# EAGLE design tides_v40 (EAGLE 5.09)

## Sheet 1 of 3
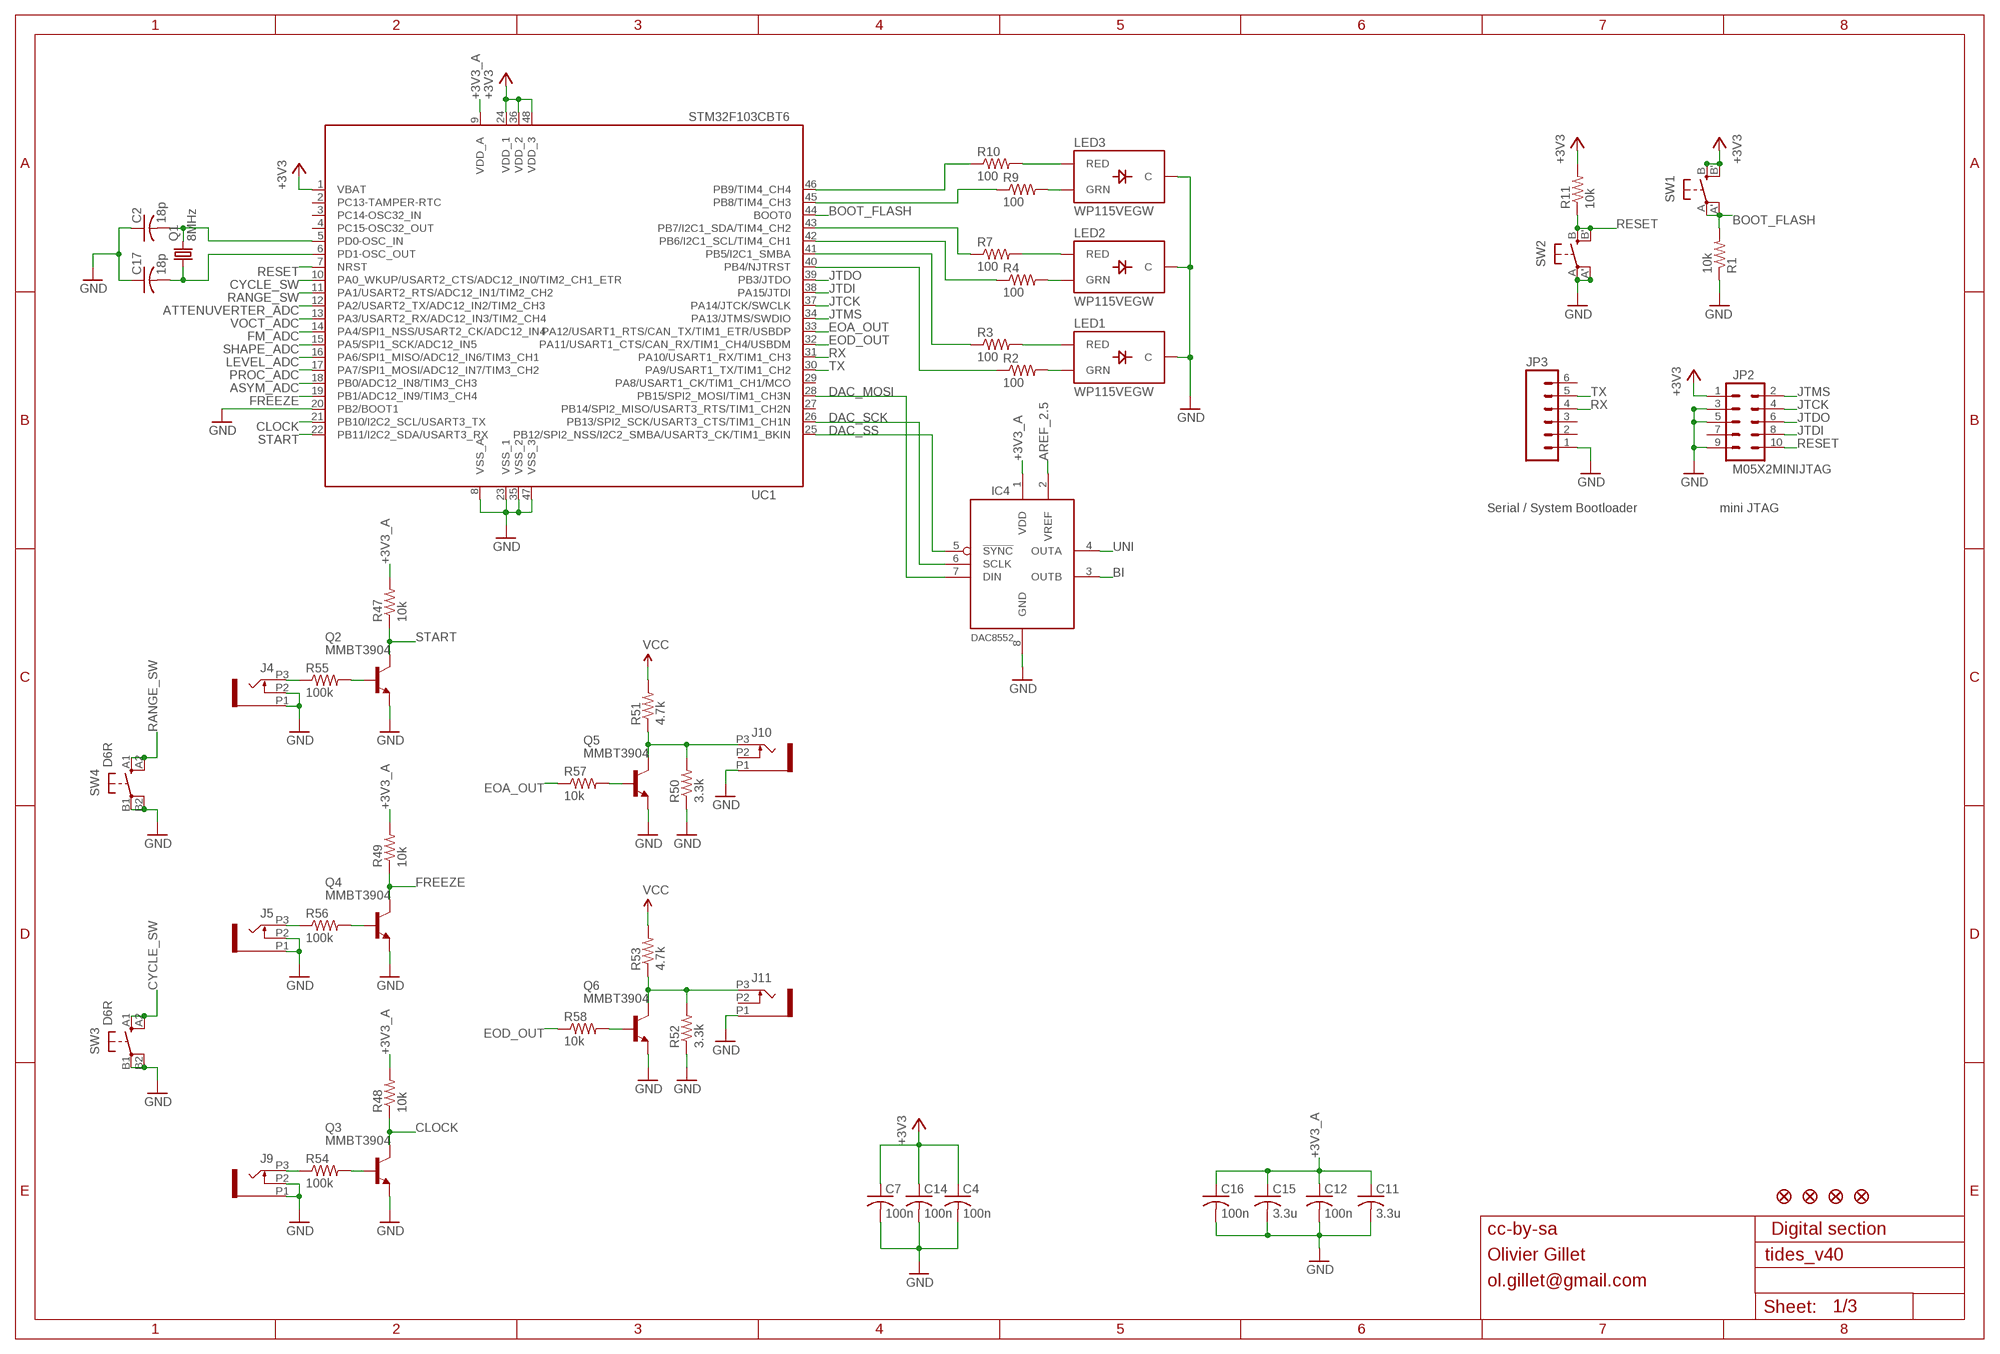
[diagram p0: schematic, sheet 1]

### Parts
C2  18p  C-USC0603  [C0603]
C4  100n  C-USC0603  [C0603]
C7  100n  C-USC0603  [C0603]
C11  3.3u  C-USC0603  [C0603]
C12  100n  C-USC0603  [C0603]
C14  100n  C-USC0603  [C0603]
C15  3.3u  C-USC0603  [C0603]
C16  100n  C-USC0603  [C0603]
C17  18p  C-USC0603  [C0603]
IC4  DAC8552  [MSOP-8]
J4  PJ301_THONKICONN6  [WQP_PJ_301M6]
J5  PJ301_THONKICONN6  [WQP_PJ_301M6]
J9  PJ301_THONKICONN6  [WQP_PJ_301M6]
J10  PJ301_THONKICONN6  [WQP_PJ_301M6]
J11  PJ301_THONKICONN6  [WQP_PJ_301M6]
JP2  M05X2MINIJTAG  [2X5-1.27]
JP3  M06SIP  [1X06]
JP4  FIDUCIAL1X2  [FIDUCIAL-1X2]
JP5  FIDUCIAL1X2  [FIDUCIAL-1X2]
JP6  FIDUCIAL1X2  [FIDUCIAL-1X2]
JP7  FIDUCIAL1X2  [FIDUCIAL-1X2]
LED1  WP115VEGW  LED-BICOLOR-THROUGHHOLE  [LED-BICOLOR-THROUGHHOLE]
LED2  WP115VEGW  LED-BICOLOR-THROUGHHOLE  [LED-BICOLOR-THROUGHHOLE]
LED3  WP115VEGW  LED-BICOLOR-THROUGHHOLE  [LED-BICOLOR-THROUGHHOLE]
Q1  8MHz  CRYSTALHC49UP  [HC49UP]
Q2  MMBT3904  MMBT3904LT1-NPN-SOT23-BEC  [SOT23-BEC]
Q3  MMBT3904  MMBT3904LT1-NPN-SOT23-BEC  [SOT23-BEC]
Q4  MMBT3904  MMBT3904LT1-NPN-SOT23-BEC  [SOT23-BEC]
Q5  MMBT3904  MMBT3904LT1-NPN-SOT23-BEC  [SOT23-BEC]
Q6  MMBT3904  MMBT3904LT1-NPN-SOT23-BEC  [SOT23-BEC]
R1  10k  R-US_R0603  [R0603]
R2  100  R-US_R0603  [R0603]
R3  100  R-US_R0603  [R0603]
R4  100  R-US_R0603  [R0603]
R7  100  R-US_R0603  [R0603]
R9  100  R-US_R0603  [R0603]
R10  100  R-US_R0603  [R0603]
R11  10k  R-US_R0603  [R0603]
R47  10k  R-US_R0603  [R0603]
R48  10k  R-US_R0603  [R0603]
R49  10k  R-US_R0603  [R0603]
R50  3.3k  R-US_R0603  [R0603]
R51  4.7k  R-US_R0603  [R0603]
R52  3.3k  R-US_R0603  [R0603]
R53  4.7k  R-US_R0603  [R0603]
R54  100k  R-US_R0603  [R0603]
R55  100k  R-US_R0603  [R0603]
R56  100k  R-US_R0603  [R0603]
R57  10k  R-US_R0603  [R0603]
R58  10k  R-US_R0603  [R0603]
SW1  EVQQ2  [EVQ-Q2]
SW2  EVQQ2  [EVQ-Q2]
SW3  D6R  [D6R]
SW4  D6R  [D6R]
UC1  STM32F103CBT6  STM32F103CB  [LQFP48]

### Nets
+3V3: C4.1 C7.1 C14.1 JP2.1 R11.2 SW1.B'(S1) SW1.B(S) UC1.1(VBAT) UC1.24(VDD_1) UC1.36(VDD_2) UC1.48(VDD_3) ; also sheet 3
+3V3_A: C11.1 C12.1 C15.1 C16.1 IC4.1(VDD) R47.2 R48.2 R49.2 UC1.9(VDD_A) ; also sheet 2,3
AREF_2.5: IC4.2(VREF) ; also sheet 3
ASYM_ADC: UC1.18(PB0/ADC12_IN8/TIM3_CH3) ; also sheet 2
ATTENUVERTER_ADC: UC1.12(PA2/USART2_TX/ADC12_IN2/TIM2_CH3) ; also sheet 2
BI: IC4.3(OUTB) ; also sheet 2
BOOT_FLASH: R1.2 SW1.A'(P1) SW1.A(P) UC1.44(BOOT0)
CLOCK: Q3.C R48.1 UC1.21(PB10/I2C2_SCL/USART3_TX)
CYCLE_SW: SW3.A1(S) SW3.A2(S1) UC1.10(PA0_WKUP/USART2_CTS/ADC12_IN0/TIM2_CH1_ETR)
DAC_MOSI: IC4.7(DIN) UC1.28(PB15/SPI2_MOSI/TIM1_CH3N)
DAC_SCK: IC4.6(SCLK) UC1.26(PB13/SPI2_SCK/USART3_CTS/TIM1_CH1N)
DAC_SS: IC4.5(!SYNC) UC1.25(PB12/SPI2_NSS/I2C2_SMBA/USART3_CK/TIM1_BKIN)
EOA_OUT: R57.1 UC1.33(PA12/USART1_RTS/CAN_TX/TIM1_ETR/USBDP)
EOD_OUT: R58.1 UC1.32(PA11/USART1_CTS/CAN_RX/TIM1_CH4/USBDM)
FM_ADC: UC1.14(PA4/SPI1_NSS/USART2_CK/ADC12_IN4) ; also sheet 2
FREEZE: Q4.C R49.1 UC1.19(PB1/ADC12_IN9/TIM3_CH4)
GND: C2.1 C4.2 C7.2 C11.2 C12.2 C14.2 C15.2 C16.2 C17.1 IC4.8(GND) J4.P1 J4.P2 J5.P1 J5.P2 J9.P1 J9.P2 J10.P1 J11.P1 JP2.3 JP2.5 JP2.9 JP3.1 LED1.2(C) LED2.2(C) LED3.2(C) Q2.E Q3.E Q4.E Q5.E Q6.E R1.1 R50.1 R52.1 SW2.A'(P1) SW2.A(P) SW3.B1(P) SW3.B2(P1) SW4.B1(P) SW4.B2(P1) UC1.8(VSS_A) UC1.20(PB2/BOOT1) UC1.23(VSS_1) UC1.35(VSS_2) UC1.47(VSS_3) ; also sheet 2,3
JTCK: JP2.4 UC1.37(PA14/JTCK/SWCLK)
JTDI: JP2.8 UC1.38(PA15/JTDI)
JTDO: JP2.6 UC1.39(PB3/JTDO)
JTMS: JP2.2 UC1.34(PA13/JTMS/SWDIO)
LEVEL_ADC: UC1.16(PA6/SPI1_MISO/ADC12_IN6/TIM3_CH1) ; also sheet 2
N$7: C2.2 Q1.2 UC1.5(PD0-OSC_IN)
N$8: C17.2 Q1.1 UC1.6(PD1-OSC_OUT)
N$21: J5.P3 R56.1
N$23: Q4.B R56.2
N$24: J9.P3 R54.1
N$25: Q3.B R54.2
N$26: Q6.B R58.2
N$27: J11.P3 Q6.C R52.2 R53.1
N$28: LED3.3(RED) R10.2
N$29: LED3.1(GRN) R9.2
N$30: LED2.3(RED) R7.2
N$31: LED2.1(GRN) R4.2
N$32: LED1.3(RED) R3.2
N$33: LED1.1(GRN) R2.2
N$34: R10.1 UC1.46(PB9/TIM4_CH4)
N$35: R9.1 UC1.45(PB8/TIM4_CH3)
N$36: R7.1 UC1.43(PB7/I2C1_SDA/TIM4_CH2)
N$37: R4.1 UC1.42(PB6/I2C1_SCL/TIM4_CH1)
N$38: R3.1 UC1.41(PB5/I2C1_SMBA)
N$39: R2.1 UC1.40(PB4/NJTRST)
N$44: J10.P3 Q5.C R50.2 R51.1
N$47: Q5.B R57.2
N$57: J4.P3 R55.1
N$66: Q2.B R55.2
PROC_ADC: UC1.17(PA7/SPI1_MOSI/ADC12_IN7/TIM3_CH2) ; also sheet 2
RANGE_SW: SW4.A1(S) SW4.A2(S1) UC1.11(PA1/USART2_RTS/ADC12_IN1/TIM2_CH2)
RESET: JP2.10 R11.1 SW2.B'(S1) SW2.B(S) UC1.7(NRST)
RX: JP3.4 UC1.31(PA10/USART1_RX/TIM1_CH3)
SHAPE_ADC: UC1.15(PA5/SPI1_SCK/ADC12_IN5) ; also sheet 2
START: Q2.C R47.1 UC1.22(PB11/I2C2_SDA/USART3_RX)
TX: JP3.5 UC1.30(PA9/USART1_TX/TIM1_CH2)
UNI: IC4.4(OUTA) ; also sheet 2
VCC: R51.2 R53.2 ; also sheet 2,3
VOCT_ADC: UC1.13(PA3/USART2_RX/ADC12_IN3/TIM2_CH4) ; also sheet 2
Unconnected: J10.P2 J11.P2 JP2.7 JP3.2 JP3.3 JP3.6 UC1.2(PC13-TAMPER-RTC) UC1.3(PC14-OSC32_IN) UC1.4(PC15-OSC32_OUT) UC1.27(PB14/SPI2_MISO/USART3_RTS/TIM1_CH2N) UC1.29(PA8/USART1_CK/TIM1_CH1/MCO)

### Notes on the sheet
- Serial / System Bootloader | mini JTAG
- cc-by-sa | Digital section
- Olivier Gillet
- ol.gillet@gmail.com

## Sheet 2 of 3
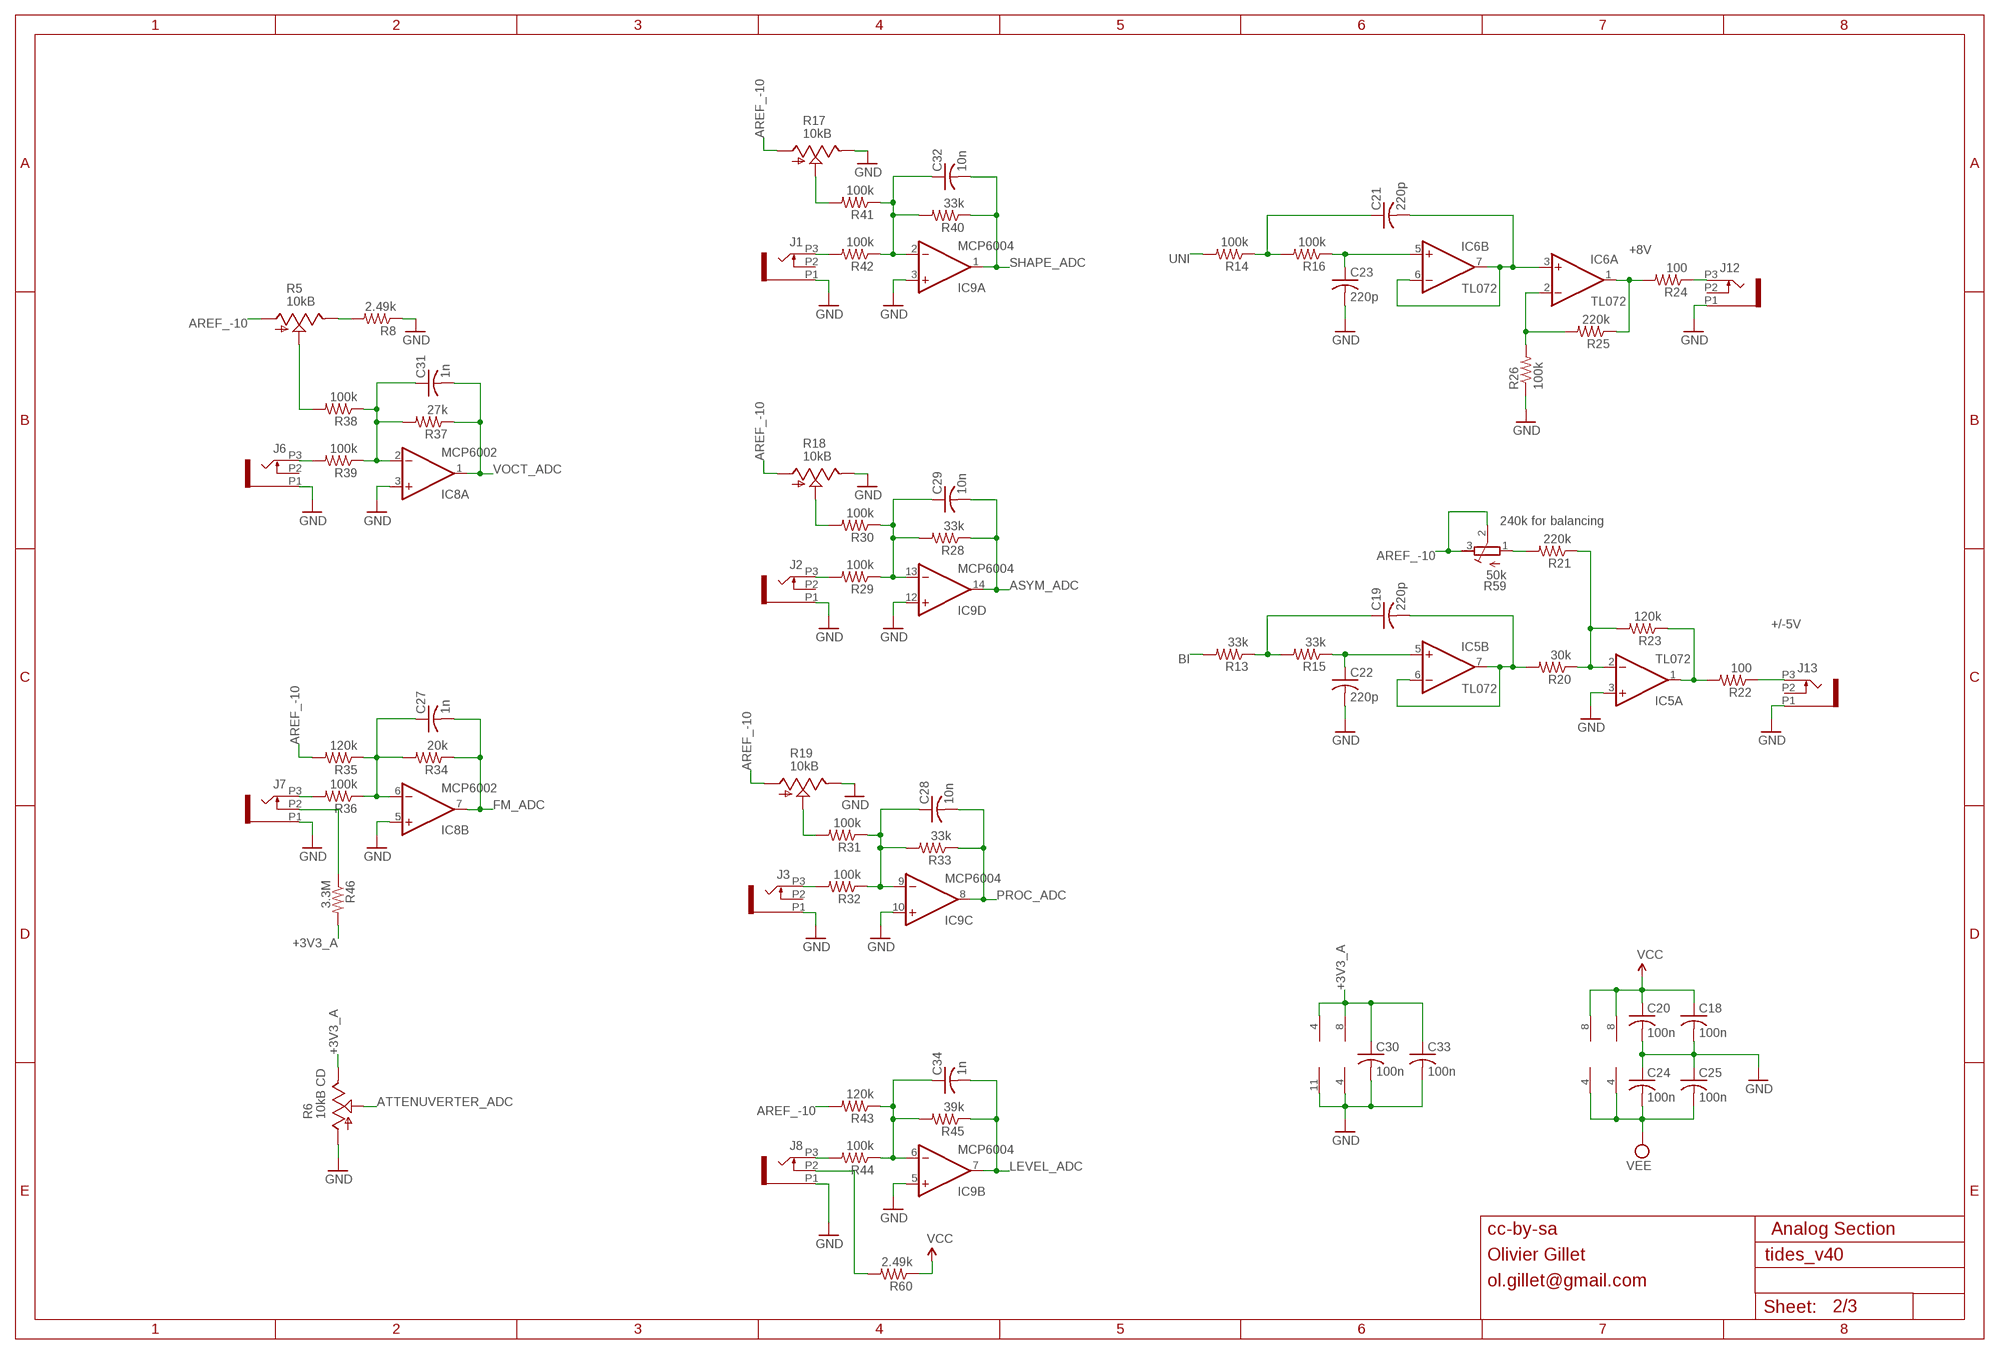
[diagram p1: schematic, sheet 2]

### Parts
C18  100n  C-USC0603  [C0603]
C19  220p  C-USC0603  [C0603]
C20  100n  C-USC0603  [C0603]
C21  220p  C-USC0603  [C0603]
C22  220p  C-USC0603  [C0603]
C23  220p  C-USC0603  [C0603]
C24  100n  C-USC0603  [C0603]
C25  100n  C-USC0603  [C0603]
C27  1n  C-USC0603  [C0603]
C28  10n  C-USC0603  [C0603]
C29  10n  C-USC0603  [C0603]
C30  100n  C-USC0603  [C0603]
C31  1n  C-USC0603  [C0603]
C32  10n  C-USC0603  [C0603]
C33  100n  C-USC0603  [C0603]
C34  1n  C-USC0603  [C0603]
IC5  TL072  TL072D  [SO08]
IC6  TL072  TL072D  [SO08]
IC8  MCP6002  TL072D  [SO08]
IC9  MCP6004  TL074D  [SO14]
J1  PJ301_THONKICONN6  [WQP_PJ_301M6]
J2  PJ301_THONKICONN6  [WQP_PJ_301M6]
J3  PJ301_THONKICONN6  [WQP_PJ_301M6]
J6  PJ301_THONKICONN6  [WQP_PJ_301M6]
J7  PJ301_THONKICONN6  [WQP_PJ_301M6]
J8  PJ301_THONKICONN6  [WQP_PJ_301M6]
J12  PJ301_THONKICONN6  [WQP_PJ_301M6]
J13  PJ301_THONKICONN6  [WQP_PJ_301M6]
R5  10kB  POT_USVERTICAL_PS  [ALPS_POT_VERTICAL_PS]
R6  10kB CD  POT_USVERTICAL_PS  [ALPS_POT_VERTICAL_PS]
R8  2.49k  R-US_R0603  [R0603]
R13  33k  R-US_R0603  [R0603]
R14  100k  R-US_R0603  [R0603]
R15  33k  R-US_R0603  [R0603]
R16  100k  R-US_R0603  [R0603]
R17  10kB  POT_USVERTICAL_PS  [ALPS_POT_VERTICAL_PS]
R18  10kB  POT_USVERTICAL_PS  [ALPS_POT_VERTICAL_PS]
R19  10kB  POT_USVERTICAL_PS  [ALPS_POT_VERTICAL_PS]
R20  30k  R-US_R0603  [R0603]
R21  220k  R-US_R0603  [R0603]
R22  100  R-US_R0603  [R0603]
R23  120k  R-US_R0603  [R0603]
R24  100  R-US_R0603  [R0603]
R25  220k  R-US_R0603  [R0603]
R26  100k  R-US_R0603  [R0603]
R28  33k  R-US_R0603  [R0603]
R29  100k  R-US_R0603  [R0603]
R30  100k  R-US_R0603  [R0603]
R31  100k  R-US_R0603  [R0603]
R32  100k  R-US_R0603  [R0603]
R33  33k  R-US_R0603  [R0603]
R34  20k  R-US_R0603  [R0603]
R35  120k  R-US_R0603  [R0603]
R36  100k  R-US_R0603  [R0603]
R37  27k  R-US_R0603  [R0603]
R38  100k  R-US_R0603  [R0603]
R39  100k  R-US_R0603  [R0603]
R40  33k  R-US_R0603  [R0603]
R41  100k  R-US_R0603  [R0603]
R42  100k  R-US_R0603  [R0603]
R43  120k  R-US_R0603  [R0603]
R44  100k  R-US_R0603  [R0603]
R45  39k  R-US_R0603  [R0603]
R46  3.3M  R-US_R0603  [R0603]
R59  50k  R-TRIMM3296X  [RTRIM3296X]
R60  2.49k  R-US_R0805  [R0805]

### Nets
+3V3_A: C30.1 C33.1 IC8.8(P:V+) IC9.4(P:V+) R6.P$1(E) R46.2 ; also sheet 1,3
AREF_-10: R5.P$3(A) R17.P$3(A) R18.P$3(A) R19.P$3(A) R35.2 R43.2 R59.2(S) R59.3(A) ; also sheet 3
ASYM_ADC: C29.2 IC9.14(D:OUT) R28.1 ; also sheet 1
ATTENUVERTER_ADC: R6.P$2(S) ; also sheet 1
BI: R13.2 ; also sheet 1
BI_OUT: IC5.1(A:OUT) R22.2 R23.1
F_CV: IC5.2(A:-IN) R20.1 R21.1 R23.2
FM_ADC: C27.2 IC8.7(B:OUT) R34.1 ; also sheet 1
GND: C18.2 C20.2 C22.2 C23.2 C24.1 C25.1 C30.2 C33.2 IC5.3(A:+IN) IC8.3(A:+IN) IC8.4(P:V-) IC8.5(B:+IN) IC9.3(A:+IN) IC9.5(B:+IN) IC9.10(C:+IN) IC9.11(P:V-) IC9.12(D:+IN) J1.P1 J2.P1 J3.P1 J6.P1 J7.P1 J8.P1 J12.P1 J13.P1 R6.P$3(A) R8.1 R17.P$1(E) R18.P$1(E) R19.P$1(E) R26.1 ; also sheet 1,3
LEVEL_ADC: C34.2 IC9.7(B:OUT) R45.1 ; also sheet 1
N$1: J1.P3 R42.2
N$2: C32.1 IC9.2(A:-IN) R40.2 R41.1 R42.1
N$3: R17.P$2(S) R41.2
N$4: J2.P3 R29.2
N$5: C29.1 IC9.13(D:-IN) R28.2 R29.1 R30.1
N$6: J7.P2 R46.1
N$9: R18.P$2(S) R30.2
N$10: J3.P3 R32.2
N$11: C28.1 IC9.9(C:-IN) R31.1 R32.1 R33.2
N$12: R19.P$2(S) R31.2
N$13: J8.P3 R44.2
N$14: C34.1 IC9.6(B:-IN) R43.1 R44.1 R45.2
N$15: J6.P3 R39.2
N$16: C31.1 IC8.2(A:-IN) R37.2 R38.1 R39.1
N$17: R5.P$2(S) R38.2
N$18: J13.P3 R22.1
N$19: R5.P$1(E) R8.2
N$20: J7.P3 R36.2
N$22: C27.1 IC8.6(B:-IN) R34.2 R35.1 R36.1
N$40: R21.2 R59.1(E)
N$41: IC6.2(A:-IN) R25.2 R26.2
N$42: C19.2 IC5.6(B:-IN) IC5.7(B:OUT) R20.2
N$43: C22.1 IC5.5(B:+IN) R15.1
N$45: C19.1 R13.1 R15.2
N$46: IC6.1(A:OUT) R24.2 R25.1
N$48: J8.P2 R60.2
N$67: C21.2 IC6.3(A:+IN) IC6.6(B:-IN) IC6.7(B:OUT)
N$69: C23.1 IC6.5(B:+IN) R16.1
N$71: C21.1 R14.1 R16.2
PROC_ADC: C28.2 IC9.8(C:OUT) R33.1 ; also sheet 1
SHAPE_ADC: C32.2 IC9.1(A:OUT) R40.1 ; also sheet 1
UNI: R14.2 ; also sheet 1
UNI_OUT: J12.P3 R24.1
VCC: C18.1 C20.1 IC5.8(P:V+) IC6.8(P:V+) R60.1 ; also sheet 1,3
VEE: C24.2 C25.2 IC5.4(P:V-) IC6.4(P:V-) ; also sheet 3
VOCT_ADC: C31.2 IC8.1(A:OUT) R37.1 ; also sheet 1
Unconnected: J1.P2 J2.P2 J3.P2 J6.P2 J12.P2 J13.P2

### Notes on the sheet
- +8V
- 240k for balancing
- +/-5V
- cc-by-sa | Analog Section
- Olivier Gillet
- ol.gillet@gmail.com

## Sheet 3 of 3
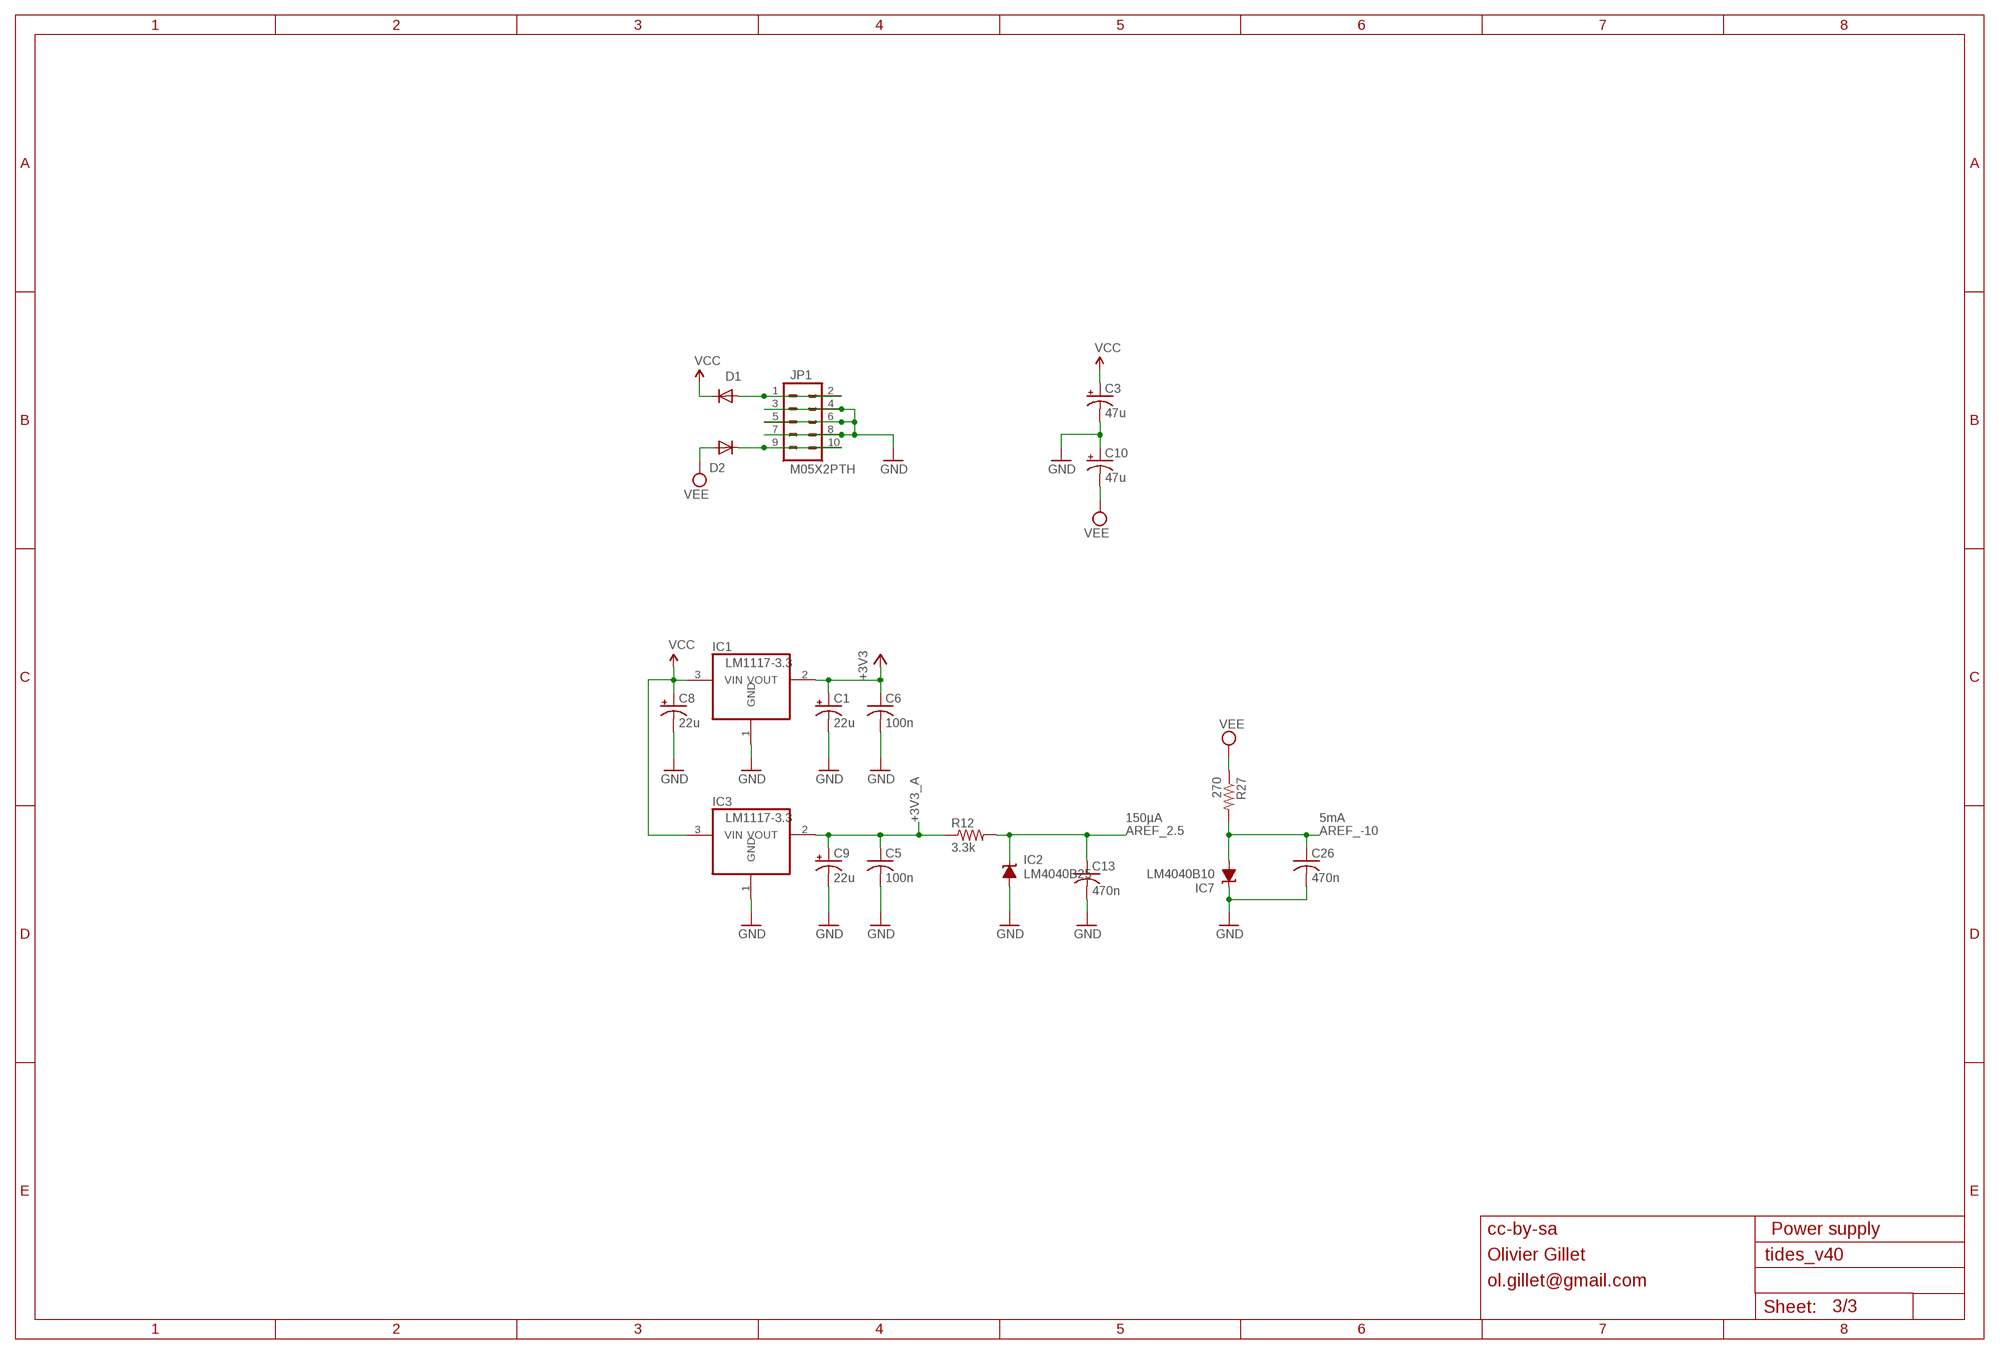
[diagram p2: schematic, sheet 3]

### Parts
C1  22u  CPOL-USC  [PANASONIC_C]
C3  47u  CPOL-USD  [PANASONIC_D]
C5  100n  C-USC0603  [C0603]
C6  100n  C-USC0603  [C0603]
C8  22u  CPOL-USC  [PANASONIC_C]
C9  22u  CPOL-USC  [PANASONIC_C]
C10  47u  CPOL-USD  [PANASONIC_D]
C13  470n  C-USC0603  [C0603]
C26  470n  C-USC0603  [C0603]
D1  1N5819HW  DIODE-SOD123  [SOD123]
D2  1N5819HW  DIODE-SOD123  [SOD123]
IC1  LM1117-3.3  REG1117  [SOT223]
IC2  LM4040B25  LM4041B12DBZ  [DBZ_R-PDSO-G3]
IC3  LM1117-3.3  REG1117  [SOT223]
IC7  LM4040B10  LM4041B12DBZ  [DBZ_R-PDSO-G3]
JP1  M05X2PTH  [AVR_ICSP]
R12  3.3k  R-US_R0603  [R0603]
R27  270  R-US_R0603  [R0603]

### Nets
+3V3: C1.+ C6.1 IC1.2(VOUT) ; also sheet 1
+3V3_A: C5.1 C9.+ IC3.2(VOUT) R12.1 ; also sheet 1,2
AREF_2.5: C13.1 IC2.1(C) R12.2 ; also sheet 1
AREF_-10: C26.1 IC7.2(A) R27.2 ; also sheet 2
GND: C1.- C3.- C5.2 C6.2 C8.- C9.- C10.+ C13.2 C26.2 IC1.1(GND) IC2.2(A) IC3.1(GND) IC7.1(C) JP1.3 JP1.4 JP1.5 JP1.6 JP1.7 JP1.8 ; also sheet 1,2
N$56: D1.A JP1.1 JP1.2
N$64: D2.C JP1.9 JP1.10
VCC: C3.+ C8.+ D1.C IC1.3(VIN) IC3.3(VIN) ; also sheet 1,2
VEE: C10.- D2.A R27.1 ; also sheet 2

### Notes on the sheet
- 150µA | 5mA
- cc-by-sa | Power supply
- Olivier Gillet
- ol.gillet@gmail.com

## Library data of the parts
C1 C3 C8-C10 = rcl:CPOL-US: POLARIZED CAPACITOR, American symbol
C2 C4-C7 C11-C34 = rcl:C-US: CAPACITOR, American symbol
D1 D2 = diode:DIODE-: DIODE
IC1 IC3 = og-vreg:REG1117: 800mA and 1A Low Dropout (LDO) Positive Regulator 1.8V, 2.5V, 2.85V, 3.3V, 5V, and Adj
IC2 IC7 = texas:LM4041: PRECISION MICROPOWER SHUNT VOLTAGE REFERENCE
IC4 = og-dac:DAC8552
IC5 IC6 IC8 = linear:TL072: OP AMP
IC9 = gm-ics:TL074: OP AMP
J1-J13 = og-pj301_variations:PJ301_THONKICONN
JP1 JP2 = og-header:M05X2: Header 5x2 Standard 10-pin dual row 0.1" header. Commonly used with AVR-ISP. Use with Spark Fun Electronics SKU: PRT-00778
JP3 = SparkFun:M06: Header 6 Standard 6-pin 0.1" header. Use with straight break away headers (SKU : PRT-00116), right angle break away headers (PRT-00553), swiss pins (PRT-00743), machine pins (PRT-00117), and female headers (PRT-00115). Molex polarized connector foot print use with SKU : PRT-08094 with associated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
JP4-JP7 = SparkFun:FIDUCIAL: Fiducial Alignment Points
LED1-LED3 = og-leds:LED-BICOLOR-THROUGHHOLE
Q1 = crystal:CRYSTAL: CRYSTAL
Q2-Q6 = transistor:*-NPN-: NPN Transistror BF959 corrected 2008.03.06
R1-R4 R7-R16 R20-R58 R60 = rcl:R-US_: RESISTOR, American symbol
R5 R6 R17-R19 = pot-alps:POT_US
R59 = rcl:R-TRIMM: Trimm resistor
SW1 SW2 = adafruit:EVQQ2: SMT 6mm switch, EVQQ2 series http://www.ladyada.net/library/eagle
SW3 SW4 = og-switch:D6R: C&K D6R
UC1 = stm32:STM32F103CB

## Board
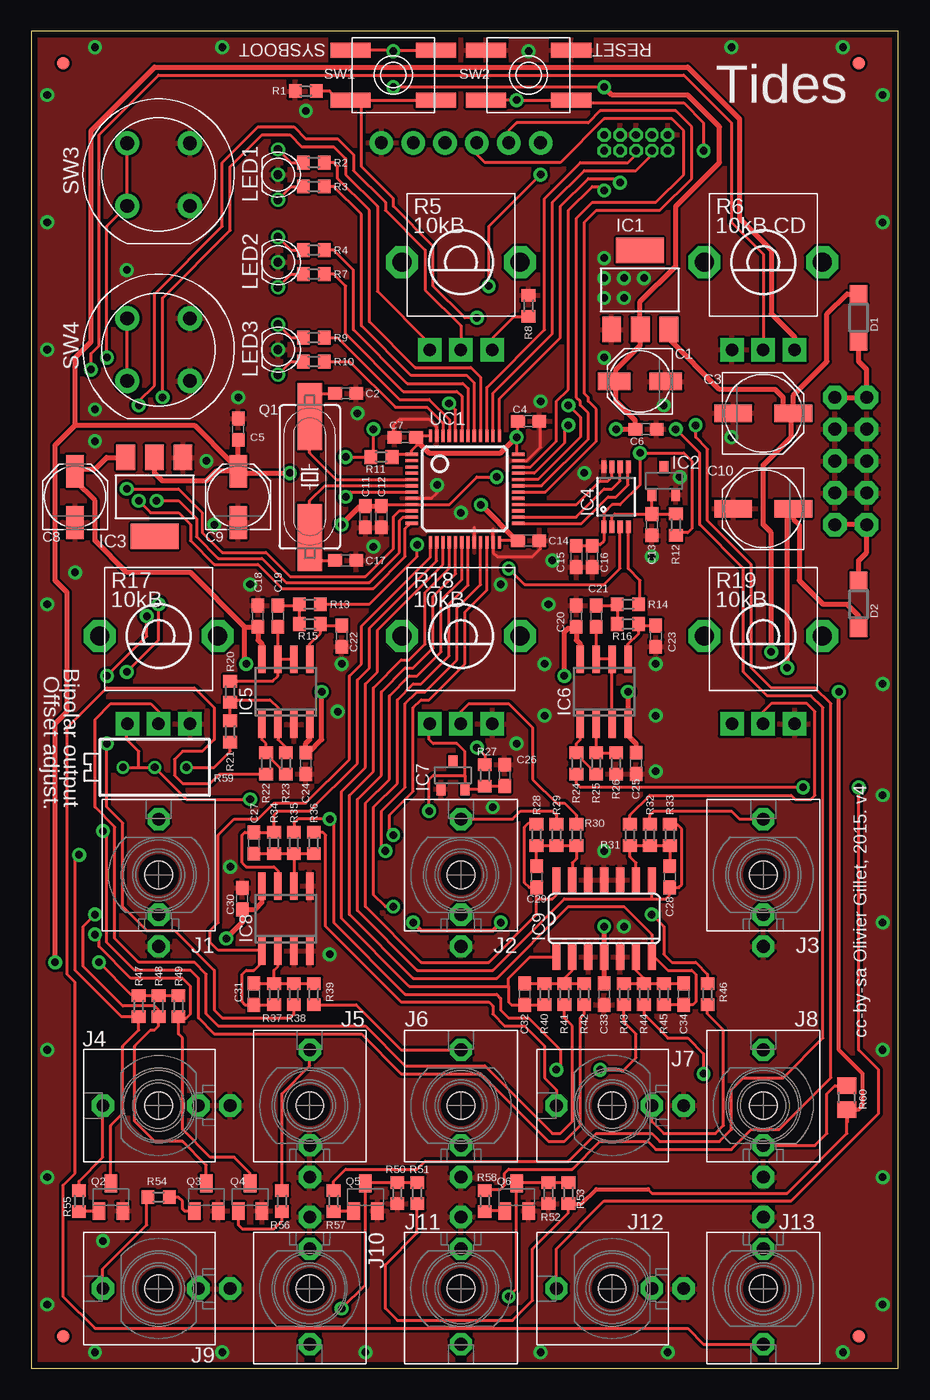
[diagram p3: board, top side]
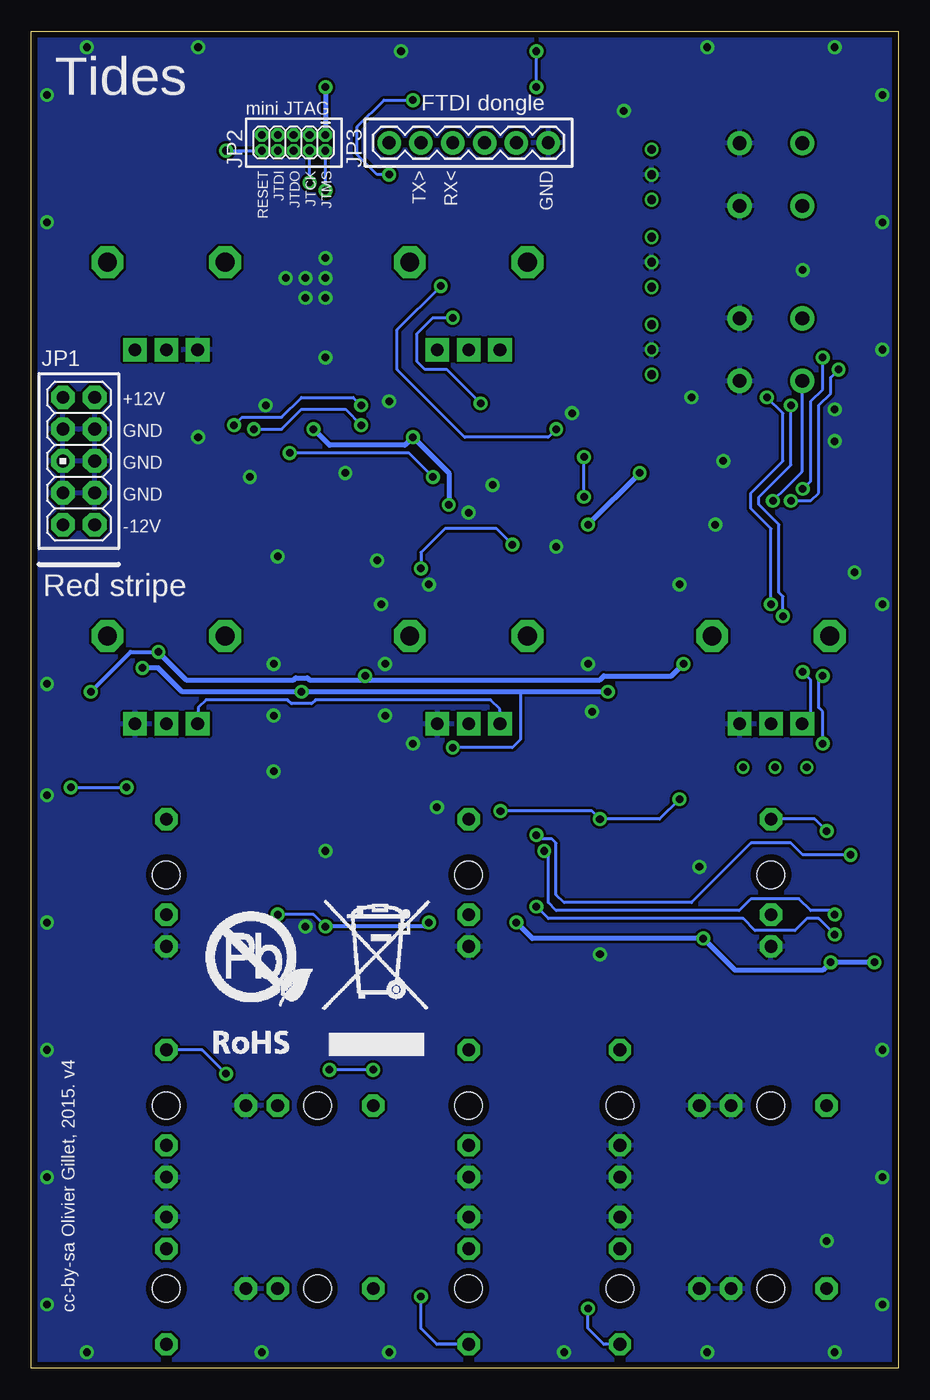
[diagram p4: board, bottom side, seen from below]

Size 69.19 x 106.68 mm. Coordinates in mm from the lower left corner, seen from the top.
Outline: 0,0 69.19,0 69.19,106.68 0,106.68 0,0
Copper layers (1*16): Top 0.035mm / dielectric 1.5mm / Bottom 0.035mm
Design rules "PCBCart-Standard": minimum track width 8mil, minimum drill 0.4mm, track to track 8mil, track to pad 8mil, pad to pad 8mil, via to via 8mil, smd to smd 8mil, copper to edge 20mil, drill to drill 8mil, minimum pad ring 8mil, minimum via ring 10mil, stop-mask expansion 3mil, vias tented up to drill 25mil, thermal gap 8mil

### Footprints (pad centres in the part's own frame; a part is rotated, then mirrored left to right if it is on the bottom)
PANASONIC_C = smd 2.6 x 1.4: + 2.05,0; - -2.05,0
C0603 = smd 1.1 x 1: 1 -0.85,0; 2 0.85,0
PANASONIC_D = smd 3 x 1.4: + 2.4,0; - -2.4,0
SOD123 = smd 1.4 x 1.4: A 1.9,0; C -1.9,0
SOT223 = smd 1.499 x 2.007: 1 -2.261,-3.15; 2 0.025,-3.15; 3 2.311,-3.15 | smd 3.81 x 2.007: 4 0,3.15
DBZ_R-PDSO-G3 = smd 0.7 x 1: 1 -0.95,-1.1; 2 0.95,-1.1; 3 0,1.1
MSOP-8 = smd 0.41 x 1.02: 1 -0.975,-2.4; 2 -0.325,-2.4; 3 0.325,-2.4; 4 0.975,-2.4; 5 0.975,2.4; 6 0.325,2.4; 7 -0.325,2.4; 8 -0.975,2.4
SO08 = smd 0.6 x 2.2: 1 -1.905,-2.6; 2 -0.635,-2.6; 3 0.635,-2.6; 4 1.905,-2.6; 5 1.905,2.6; 6 0.635,2.6; 7 -0.635,2.6; 8 -1.905,2.6
SO14 = smd 0.66 x 2.032: 1 -3.81,-3.073; 2 -2.54,-3.073; 3 -1.27,-3.073; 4 0,-3.073; 5 1.27,-3.073; 6 2.54,-3.073; 7 3.81,-3.073; 8 3.81,3.073; 9 2.54,3.073; 10 1.27,3.073; 11 0,3.073; 12 -1.27,3.073; 13 -2.54,3.073; 14 -3.81,3.073
WQP_PJ_301M6 = drill 1.016 pad 1.778 octagon: P1 0,-5.715; P2 0,-3.175; P3 0,4.445 | hole 2.2: 0,0
AVR_ICSP = drill 1.016 pad 1.88 octagon: 1 -1.27,5.08; 2 1.27,5.08; 3 -1.27,2.54; 4 1.27,2.54; 5 -1.27,0; 6 1.27,0; 7 -1.27,-2.54; 8 1.27,-2.54; 9 -1.27,-5.08; 10 1.27,-5.08
2X5-1.27 = drill 0.61 pad 1.067 octagon: 1 -1.27,3.81; 2 0,3.81; 3 -1.27,2.54; 4 0,2.54; 5 -1.27,1.27; 6 0,1.27; 7 -1.27,0; 8 0,0; 9 -1.27,-1.27; 10 0,-1.27
1X06 = drill 1.016 pad 1.88 round: 1 0,0; 2 2.54,0; 3 5.08,0; 4 7.62,0; 5 10.16,0; 6 12.7,0
FIDUCIAL-1X2 = smd 1 x 1: 1 0,0
LED-BICOLOR-THROUGHHOLE = drill 0.7 round: 1 -2,0; 2 0,0; 3 2,0
HC49UP = smd 5.334 x 1.93: 1 -4.826,0; 2 4.826,0
SOT23-BEC = smd 1 x 1.4: B -0.95,-1.1; C 0,1.1; E 0.95,-1.1
R0603 = smd 1 x 1.1: 1 -0.85,0; 2 0.85,0
ALPS_POT_VERTICAL_PS = drill 1 pad 1.88 square: P$1 -2.5,7; P$2 0,7; P$3 2.5,7 | drill 1.5 pad 2.54 octagon: P$4 -4.7,0; P$5 4.7,0
RTRIM3296X = drill 0.61 round: 1 0,-2.54; 2 0,0; 3 0,2.54
R0805 = smd 1.3 x 1.5: 1 -0.95,0; 2 0.95,0
EVQ-Q2 = smd 3.2 x 1.2: A -3.4,-2; A' 3.4,-2; B -3.4,2; B' 3.4,2
D6R = drill 1.1 pad 1.93 round: A1 -2.5,2.5; A2 2.5,2.5; B1 -2.5,-2.5; B2 2.5,-2.5
LQFP48 = smd 0.254 x 1: 1 -2.75,-4.25; 2 -2.25,-4.25; 3 -1.75,-4.25; 4 -1.25,-4.25; 5 -0.75,-4.25; 6 -0.25,-4.25; 7 0.25,-4.25; 8 0.75,-4.25; 9 1.25,-4.25; 10 1.75,-4.25; 11 2.25,-4.25; 12 2.75,-4.25; 25 2.75,4.25; 26 2.25,4.25; 27 1.75,4.25; 28 1.25,4.25; 29 0.75,4.25; 30 0.25,4.25; 31 -0.25,4.25; 32 -0.75,4.25; 33 -1.25,4.25; 34 -1.75,4.25; 35 -2.25,4.25; 36 -2.75,4.25 | smd 1 x 0.254: 13 4.25,-2.75; 14 4.25,-2.25; 15 4.25,-1.75; 16 4.25,-1.25; 17 4.25,-0.75; 18 4.25,-0.25; 19 4.25,0.25; 20 4.25,0.75; 21 4.25,1.25; 22 4.25,1.75; 23 4.25,2.25; 24 4.25,2.75; 37 -4.25,2.75; 38 -4.25,2.25; 39 -4.25,1.75; 40 -4.25,1.25; 41 -4.25,0.75; 42 -4.25,0.25; 43 -4.25,-0.25; 44 -4.25,-0.75; 45 -4.25,-1.25; 46 -4.25,-1.75; 47 -4.25,-2.25; 48 -4.25,-2.75

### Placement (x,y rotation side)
C1  48.58,78.74 180 top
C2  25.08,77.79 180 top
C3  58.42,76.2 0 top
C4  39.69,75.56 0 top
C5  16.51,74.93 90 top
C6  49.05,74.93 0 top
C7  29.84,74.3 180 top
C8  3.49,69.53 90 top
C9  16.51,69.53 90 top
C10  58.42,68.58 180 top
C11  26.67,67.94 270 top
C12  27.94,67.94 270 top
C13  49.53,67.31 270 top
C14  39.69,66.04 0 top
C15  43.5,64.77 270 top
C16  44.77,64.77 270 top
C17  25.08,64.45 180 top
C18  18.1,60.01 90 top
C19  19.68,60.01 270 top
C20  43.5,60.01 90 top
C21  45.09,60.01 270 top
C22  24.77,58.42 270 top
C23  49.85,58.42 270 top
C24  21.91,48.26 90 top
C25  48.26,48.26 90 top
C26  37.78,47.31 90 top
C27  17.78,41.91 90 top
C28  50.96,39.21 270 top
C29  40.32,39.21 270 top
C30  16.83,37.47 90 top
C31  17.78,29.84 270 top
C32  39.37,29.84 270 top
C33  45.72,29.84 270 top
C34  52.07,29.84 270 top
D1  66.04,83.82 270 top
D2  66.04,60.96 270 top
IC1  48.58,86.04 0 top
IC2  50.48,70.8 0 top
IC3  9.84,69.53 180 top
IC4  46.67,69.53 0 top
IC5  20.32,53.98 0 top
IC6  45.72,53.98 0 top
IC7  33.66,47.31 0 top
IC8  20.32,35.88 0 top
IC9  45.72,35.88 0 top
J1  10.16,39.37 0 top
J2  34.29,39.37 0 top
J3  58.42,39.37 0 top
J4  10.16,20.95 90 top
J5  22.23,20.95 0 top
J6  34.29,20.95 0 top
J7  46.35,20.95 90 top
J8  58.42,20.95 0 top
J9  10.16,6.35 90 top
J10  22.23,6.35 180 top
J11  34.29,6.35 180 top
J12  46.35,6.35 90 top
J13  58.42,6.35 180 top
JP1  65.41,72.39 0 bottom
JP2  49.53,97.16 270 bottom
JP3  27.94,97.79 180 bottom
JP4  2.54,104.14 0 top
JP5  66.04,104.14 0 top
JP6  2.54,2.54 0 top
JP7  66.04,2.54 0 top
LED1  19.68,95.25 270 top
LED2  19.68,88.27 270 top
LED3  19.68,81.28 270 top
Q1  22.23,71.12 90 top
Q2  6.35,13.65 0 top
Q3  13.97,13.65 0 top
Q4  17.46,13.65 0 top
Q5  26.67,13.65 0 top
Q6  38.73,13.65 0 top
R1  21.91,101.92 0 top
R2  22.54,96.2 180 top
R3  22.54,94.3 180 top
R4  22.54,89.22 180 top
R5  34.29,88.27 180 top
R6  58.42,88.27 180 top
R7  22.54,87.31 180 top
R8  39.69,84.77 270 top
R9  22.54,82.23 180 top
R10  22.54,80.33 180 top
R11  27.94,72.71 0 top
R12  51.44,67.31 90 top
R13  22.23,60.96 0 top
R14  47.62,60.96 0 top
R15  22.23,59.37 180 top
R16  47.62,59.37 180 top
R17  10.16,58.42 180 top
R18  34.29,58.42 180 top
R19  58.42,58.42 180 top
R20  15.88,53.98 90 top
R21  15.88,50.8 270 top
R22  18.73,48.26 90 top
R23  20.32,48.26 90 top
R24  43.5,48.26 90 top
R25  45.09,48.26 90 top
R26  46.67,48.26 90 top
R27  36.2,47.31 270 top
R28  40.32,42.55 270 top
R29  41.91,42.55 90 top
R30  43.5,42.55 90 top
R31  47.78,42.55 90 top
R32  49.37,42.55 90 top
R33  50.96,42.55 270 top
R34  19.37,41.91 270 top
R35  20.95,41.91 90 top
R36  22.54,41.91 90 top
R37  19.37,29.84 90 top
R38  20.95,29.84 270 top
R39  22.54,29.84 270 top
R40  40.96,29.84 90 top
R41  42.55,29.84 270 top
R42  44.13,29.84 270 top
R43  47.31,29.84 270 top
R44  48.9,29.84 270 top
R45  50.48,29.84 90 top
R46  53.98,29.84 90 top
R47  8.57,28.89 90 top
R48  10.16,28.89 90 top
R49  11.75,28.89 90 top
R50  29.21,13.97 90 top
R51  30.8,13.97 270 top
R52  41.27,13.97 90 top
R53  42.86,13.97 270 top
R54  10.16,13.65 0 top
R55  3.81,13.34 270 top
R56  20,13.34 270 top
R57  24.13,13.34 270 top
R58  36.2,13.34 270 top
R59  9.84,47.94 90 top
R60  65.09,21.59 90 top
SW1  28.89,103.19 0 top
SW2  39.69,103.19 180 top
SW3  10.16,95.25 90 top
SW4  10.16,81.28 90 top
U$3  [ROHS_BIG]  56.52,24.13 0 bottom
UC1  34.61,70.17 270 top

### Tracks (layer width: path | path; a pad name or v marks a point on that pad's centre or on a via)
+3V3  (via drill 0.6)
  Top 0.254: 32.38,105.09 SW1.B' 28.99,105.19 v28.89,105.09 28.8,105.19 SW1.B | C7.1 30.82,74.42 UC1.48 | 30.7,74.08 30.8,73.98 30.8,73.66 30.36,73.22 UC1.1 29,72.92 R11.2 | C4.1 38.84,74.4 v38.73,74.3 38.73,73.04 UC1.36 | v45.72,102.23 v28.89,102.23 | UC1.24 37.48,66.04 C14.1
  Top 0.406: v45.72,102.23 46.35,101.6 52.39,101.6 54.93,99.06 54.93,96.2 51.44,92.71 51.44,87.95 48.58,85.09 48.58,82.92 IC1.2 48.6,81.62 46.67,79.69 46.67,78.89 C1.+ 46.67,78.59 46.67,77.15 48.2,75.62 C6.1 v46.67,74.93 | v38.73,74.3 37.47,73.03 31.75,73.03 30.7,74.08 C7.1 | v35.88,68.9 38.73,66.04 C14.1
  Bottom 0.254: v28.89,102.23 v28.89,105.09 28.89,105.19
  Bottom 0.406: v45.72,102.23 JP2.1 | v46.67,74.93 45.4,73.66 39.37,73.66 v38.73,74.3 35.88,71.44 v35.88,68.9
+3V3_A  (via drill 0.6)
  Top 0.254: C12.1 28.06,68.92 UC1.9 33.36,68.92 35.56,71.12 v37.15,71.12 | C15.1 C16.1 44.87,65.72 45.4,65.72 45.7,66.02 IC4.1 45.7,68.24 46.35,68.9 46.99,68.9 48.58,70.48 v48.58,73.03 52.07,73.03 52.7,72.39 52.7,66.99 52.39,66.67 51.65,66.67 R12.1 | R6.P$1 60.96,81.31 | v5.4,32.38 7.94,29.84 8.47,29.84 R47.2 R48.2 R49.2 | R46.2 53.98,31.43 53.02,32.38 51.12,32.38 50.48,33.02 50.48,35.24 v49.53,36.2
  Top 0.305: v30.48,35.56 31.11,34.92 36.83,34.92 v37.47,35.56
  Top 0.406: IC3.2 9.84,72.66 9.84,71.44 10.48,70.8 13.97,70.8 14.75,71.58 C9.+ | 16.51,72.39 C5.1 | C9.+ 16.68,71.75 17,71.44 v20.64,71.44 | 16.51,72.39 C9.+ | 16.51,72.39 15.88,72.39 13.02,75.25 3.49,75.25 | v45.72,35.24 IC9.4 C33.1 | IC8.8 18.41,37.15 17.88,36.62 C30.1 16.83,35.56 v15.56,34.29 | v24.77,67.31 26.25,68.8 C11.1 C12.1 | R6.P$1 60.92,82.27 59.05,84.14 59.05,89.22 56.52,91.76 56.52,99.69 52.39,103.82 9.84,103.82 4.76,98.74 4.76,81.92 3.49,80.64 3.49,75.25 | v1.91,32.38 1.91,51.44 2.86,52.39 2.86,61.91 1.91,62.87 1.91,73.66 3.49,75.25
  Bottom 0.254: v48.58,73.03 39.05,73.03 v37.15,71.12 | v49.53,36.2 46.67,36.2 v45.72,35.24
  Bottom 0.305: v37.47,35.56 37.78,35.24 v45.72,35.24
  Bottom 0.406: v20.64,71.44 v24.77,67.31 | v30.48,35.56 29.21,34.29 v15.56,34.29 13.02,31.75 6.03,31.75 v5.4,32.38 v1.91,32.38
AREF_2.5
  Top 0.254: IC4.2 46.35,67.94 46.57,68.16 C13.1 | C13.1 IC2.1 | C13.1 R12.2
AREF_-10  (via drill 0.6)
  Top 0.254: C26.1 R27.2 35.95,46.21 IC7.2 | R18.P$3 31.75,51.38 31.75,50.16 32.07,49.85 33.97,49.85 34.6,49.22 34.6,47.31 | IC7.2 | R35.2 20.95,43.5 21.27,43.81 v23.81,43.81 24.13,43.5 24.13,35.56 29.84,29.84 37.15,29.84 37.47,29.53 37.47,28.57 38.1,27.94 39.69,27.94 42.23,25.4 42.23,24.13 v41.91,23.81 | v45.4,23.81 47.31,23.81 48.26,24.77 48.26,26.67 47.31,27.62 R43.2 | v10.16,60.96 10.16,58.1 v7.62,55.56 | 34.6,47.31 IC7.2 | v31.75,44.45 31.75,46.99 32.07,47.31 34.6,47.31 | v10.48,77.47 10.48,85.41 15.88,90.81 15.88,95.89 18.41,98.42 20.64,98.42 21.59,97.47 24.13,97.47 25.08,96.52 25.08,95.25 27.62,92.71 27.62,85.94 31.79,81.77 R5.P$3 | R59.3 8.57,47.94 | 8.57,47.94 R59.2 12.38,45.4 v17.46,45.4 | R17.P$3 7.62,51.38 7.62,50.16 8.57,49.21 8.57,47.94
  Bottom 0.254: v31.75,44.45 24.45,44.45 v23.81,43.81 19.05,43.81 v17.46,45.4 | v41.91,23.81 v45.4,23.81 | v10.48,77.47 9.21,76.2 9.21,72.39 11.75,69.85 11.75,68.58 10.16,66.99 v10.16,60.96 | v7.62,55.56 6.99,54.93 6.99,52.09 R17.P$3 | R19.P$3 55.88,51.46 55.88,52.7 55.24,53.34 48.74,53.34 48.42,53.02 46.83,53.02 46.51,53.34 32.54,53.34 31.79,52.59 R18.P$3
ASYM_ADC
  Top 0.254: UC1.18 34.36,62.93 32.7,61.28 32.7,57.15 30.8,55.24 30.16,55.24 28.57,53.66 28.57,46.99 26.67,45.09 26.67,36.83 31.11,32.38 36.51,32.38 40.32,36.2 40.32,37.47 | R28.1 40.22,43.5 39.69,43.5 39.37,43.18 39.37,38.73 39.74,38.36 C29.2 40.32,37.47 | IC9.14 41.91,37.78 41.59,37.47 40.32,37.47
ATTENUVERTER_ADC  (via drill 0.6)
  Top 0.254: R6.P$2 58.42,88.9 55.88,91.44 55.88,99.38 52.07,103.19 10.16,103.19 5.4,98.42 5.4,81.6 4.76,80.96 v4.76,79.69 | v8.57,69.22 9.53,68.26 11.75,68.26 12.7,67.31 12.7,66.04 14.61,64.14 18.1,64.14 20,62.23 27.3,62.23 29.84,64.77 29.84,66.99 30.27,67.42 UC1.12
  Bottom 0.254: v4.76,79.69 5.4,79.06 5.4,77.79 6.35,76.83 6.35,69.85 6.99,69.22 v8.57,69.22
BI  (via drill 0.6)
  Top 0.254: IC4.3 46.99,63.82 45.72,62.55 39.37,62.55 v38.1,63.82 | R13.2 26.99,60.96 30.8,64.77 v30.8,65.72
  Bottom 0.254: v30.8,65.72 32.07,66.99 36.2,66.99 38.1,65.09 v38.1,63.82
BI_OUT
  Top 0.254: IC5.1 18.41,50.16 18.73,49.85 R22.2 18.73,49 R23.1
BOOT_FLASH  (via drill 0.6)
  Top 0.254: 26.35,101.19 SW1.A | 26.35,101.19 SW1.A' | SW1.A 25.4,101.09 | v33.34,76.99 33.86,76.47 UC1.44 | 26.35,101.19 26.35,95.89 28.89,93.34 28.89,92.71 32.07,89.53 32.07,86.36 34.61,83.82 v35.56,83.82 | R1.2 23.81,101.92 24.54,101.19 SW1.A
  Bottom 0.254: v33.34,76.99 36.04,79.69 37.78,79.69 38.42,80.33 38.42,82.55 37.15,83.82 v35.56,83.82
CLOCK  (via drill 0.6)
  Top 0.254: Q3.C 13.97,16.19 12.06,18.1 9.84,18.1 8.26,19.68 8.26,25.72 9.53,26.99 9.84,26.99 10.16,27.3 R48.1 10.16,28.57 9.84,28.89 7.3,28.89 4.13,32.07 4.13,35.24 v5.08,36.2 | UC1.21 35.86,62.53 33.97,60.64 33.97,56.52 31.43,53.98 30.8,53.98 29.84,53.02 29.84,46.35 27.94,44.45 27.94,41.59 v28.26,41.27
  Bottom 0.254: v28.26,41.27 27.94,40.96 27.94,37.15 27.3,36.51 12.7,36.51 11.75,37.47 7.94,37.47 6.99,36.51 5.4,36.51 v5.08,36.2
CYCLE_SW  (via drill 0.6)
  Top 0.254: SW3.A2 SW3.A1 6.03,91.12 v6.03,80.64 | UC1.10 29.37,68.42 28.89,67.94 28.89,65.41 26.67,63.18 20.64,63.18 18.73,65.09 15.24,65.09 13.65,66.67 13.65,68.26 11.75,70.17 v7.62,70.17
  Bottom 0.254: v7.62,70.17 6.99,70.8 6.99,77.15 6.03,78.11 v6.03,80.64
DAC_MOSI
  Top 0.254: IC4.7 46.35,71.12 46.04,70.8 45.4,70.8 43.52,68.92 UC1.28
DAC_SCK
  Top 0.254: IC4.6 46.99,70.8 46.35,70.17 45.72,70.17 43.47,67.92 UC1.26
DAC_SS
  Top 0.254: IC4.5 47.62,71.91 47.62,70.48 46.67,69.53 46.04,69.53 43.92,67.42 UC1.25
EOA_OUT  (via drill 0.6)
  Top 0.254: UC1.33 40.14,71.42 42.55,73.82 42.55,74.93 v42.86,75.25 | v51.44,74.93 53.34,73.03 53.34,67.31 56.83,63.82 56.83,55.56 58.74,53.66 62.23,53.66 63.18,52.7 63.18,26.35 60.01,23.18 56.83,23.18 55.88,22.23 55.88,19.05 54.93,18.1 50.16,18.1 49.53,18.73 45.09,18.73 42.86,16.51 31.43,16.51 30.8,15.88 25.08,15.88 24.13,14.92 R57.1
  Bottom 0.254: v51.44,74.93 49.21,74.93 47.62,76.52 44.13,76.52 v42.86,75.25
EOD_OUT  (via drill 0.6)
  Top 0.254: UC1.32 40.44,70.92 43.81,74.3 43.81,75.88 v42.86,76.83 | v53.02,75.25 53.02,74.3 53.98,73.34 53.98,67.63 57.47,64.14 57.47,55.88 59.05,54.29 62.55,54.29 63.82,53.02 63.82,23.18 59.69,19.05 57.47,19.05 55.88,17.46 49.85,17.46 49.21,18.1 45.4,18.1 43.18,15.88 38.1,15.88 37.78,15.56 37.78,14.61 37.47,14.29 36.3,14.29 R58.1
  Bottom 0.254: v53.02,75.25 52.39,75.88 49.21,75.88 47.62,77.47 43.5,77.47 v42.86,76.83
F_CV
  Top 0.254: R23.2 20.32,49.53 19.68,50.16 IC5.2 19.68,52.7 19.05,53.34 16.09,53.34 R20.1 R21.1
FM_ADC
  Top 0.254: IC8.7 19.68,39.69 19.37,40.01 17.14,40.01 16.83,40.32 16.83,42.55 17.04,42.76 C27.2 R34.1 19.37,44.13 19.68,44.45 22.23,44.45 26.04,48.26 26.04,54.93 26.99,55.88 26.99,59.05 32.36,64.42 UC1.14
FREEZE  (via drill 0.6)
  Top 0.254: Q4.C 17.46,15.56 16.19,16.83 14.29,16.83 12.06,19.05 12.06,26.35 11.75,26.67 R49.1 11.85,27.94 12.38,27.94 12.7,28.26 12.7,30.48 12.06,31.11 7.94,31.11 5.4,33.66 5.4,34.29 v5.08,34.61 | UC1.19 34.86,62.48 33.34,60.96 33.34,56.83 31.11,54.61 30.48,54.61 29.21,53.34 29.21,46.67 27.3,44.77 27.3,37.78 28.26,36.83 v28.89,36.83
  Bottom 0.254: v28.89,36.83 27.94,35.88 12.38,35.88 11.43,34.92 8.26,34.92 7.3,35.88 6.35,35.88 v5.08,34.61
GND  (via drill 0.6)
  Top 0.254: C4.2 40.64,75.46 40.64,73.5 39.56,72.42 UC1.35 | v32.38,70.48 32.38,69.85 31.95,69.42 UC1.8 | C7.2 28.89,74.4 28.89,75.25 29.37,75.72 31.75,75.72 32.36,75.12 UC1.47 | UC1.20 35.36,67.11 | 36.86,66.97 UC1.23 36.86,65.06 37.15,64.77 40.01,64.77 40.64,65.41 40.64,65.94 C14.2
  other vias: 49.85,56.2 51.75,71.12 17.46,62.55 41.59,64.45 40.64,77.15 26.04,76.2 27.3,65.56 14.61,67.31 13.97,72.39 50.48,76.83 55.88,74.3 45.72,85.41 39.69,105.09 21.91,100.33 24.77,56.2 49.85,47.62 15.88,40.01 47.31,35.24 45.72,41.27 36.83,44.77 34.29,68.26 41.27,60.96 49.53,64.77 16.51,77.47 3.49,63.5 38.73,49.85 24.45,52.39 40.96,56.2 23.81,33.02 40.96,52.07 7.62,87.63 5.08,105.41 15.24,105.41 55.88,105.41 64.77,105.41 1.27,101.6 1.27,91.44 1.27,81.28 1.27,60.96 1.27,25.4 1.27,15.24 1.27,5.08 5.08,1.27 15.24,1.27 26.67,1.27 40.64,1.27 50.8,1.27 64.77,1.27 67.94,5.08 67.94,15.24 67.94,25.4 67.94,35.56 67.94,45.72 67.94,54.61 67.94,101.6 67.94,91.44 37.47,62.55 44.13,71.44 49.85,52.07 45.72,87 47.31,87 48.9,87 45.72,80.64 45.72,88.58 47.31,85.41 5.08,73.98 5.08,76.52 5.71,10.16
  pour Bottom: 0,106.68 0,0 69.22,0 69.22,106.68
  pour Top (isolate 0.203): 0,106.68 0,0 69.22,0 69.22,106.68
JTCK  (via drill 0.6)
  Top 0.254: v46.99,94.61 46.67,94.93 44.45,94.93 42.23,92.71 42.23,82.23 37.36,77.36 UC1.37
  Bottom 0.254: v46.99,94.61 JP2.4
JTDI
  Top 0.254: JP2.8 49.53,96.84 48.26,95.57 44.13,95.57 41.59,93.03 41.59,82.55 36.86,77.81 UC1.38
JTDO
  Top 0.254: JP2.6 48.26,96.84 47.62,96.2 43.81,96.2 40.96,93.34 40.96,82.87 36.36,78.27 UC1.39
JTMS  (via drill 0.6)
  Top 0.254: v45.72,93.98 45.4,94.3 44.77,94.3 42.86,92.39 42.86,78.11 41.91,77.15 41.91,73.98 39.85,71.92 UC1.34
  Bottom 0.254: v45.72,93.98 JP2.2
LEVEL_ADC
  Top 0.254: R45.1 C34.2 52.81,29 53.02,29.21 53.02,31.43 52.7,31.75 50.8,31.75 49.75,32.8 IC9.7 49.53,34.61 47.31,36.83 42.86,36.83 37.15,31.11 30.48,31.11 25.4,36.2 25.4,45.72 27.3,47.62 27.3,54.29 29.53,56.52 30.16,56.52 31.43,57.78 31.43,61.91 33.36,63.84 UC1.16
N$1  (via drill 0.6)
  Top 0.254: R42.2 44.13,28.26 43.81,27.94 43.81,19.37 42.55,18.1 41.27,18.1 35.88,23.5 29.53,23.5 26.35,26.67 14.61,26.67 13.34,27.94 13.34,31.11 12.7,31.75 8.26,31.75 6.03,33.97 6.03,42.55 v5.71,42.86
  Bottom 0.254: v5.71,42.86 6.67,43.81 J1.P3
N$2
  Top 0.254: C32.1 39.37,30.8 39.47,30.7 R40.2 R41.1 | R41.1 R42.1 | IC9.2 43.18,31.75 42.55,31.11 R41.1
N$3
  Top 0.254: R17.P$2 10.16,52.39 9.53,53.02 6.35,53.02 5.08,51.75 5.08,44.77 6.67,43.18 6.67,34.29 8.57,32.38 13.02,32.38 13.97,31.43 13.97,28.26 14.92,27.3 26.67,27.3 29.84,24.13 36.2,24.13 41.59,18.73 42.23,18.73 43.18,19.68 43.18,27.3 42.55,27.94 R41.2
N$4
  Top 0.254: R29.2 41.91,44.13 41.59,44.45 39.05,44.45 38.42,43.81 J2.P3
N$5
  Top 0.254: C29.1 | C29.1 R28.2 R29.1 R30.1 43.5,40.64 43.18,40.32 IC9.13
N$6
  Top 0.254: R46.1 53.98,28.26 55.24,26.99 55.24,19.37 54.61,18.73 50.48,18.73 49.53,19.68 J7.P2
N$7
  Top 0.254: UC1.5 24.33,70.92 22.23,73.03 Q1.2 22.23,77.47 22.54,77.79 C2.2
N$8
  Top 0.254: UC1.6 23.43,70.42 22.23,69.22 Q1.1 22.23,64.77 22.54,64.45 C17.2
N$9
  Top 0.254: R30.2 43.5,44.13 42.55,45.09 41.91,45.09 40.01,46.99 40.01,51.12 38.1,53.02 34.92,53.02 34.29,52.39 R18.P$2
N$10
  Top 0.254: R32.2 49.37,44.13 49.69,44.45 55.88,44.45 56.52,43.81 J3.P3
N$11
  Top 0.254: C28.1 R33.2 R32.1 R31.1 47.78,40.8 48.26,40.32 IC9.9
N$12
  Top 0.254: R31.2 47.78,44.13 49.37,45.72 60.64,45.72 60.96,45.4 62.23,45.4 62.55,45.72 62.55,52.39 61.91,53.02 59.05,53.02 58.42,52.39 R19.P$2
N$13  (via drill 0.6)
  Top 0.254: R44.2 48.9,28.26 50.8,26.35 52.39,26.35 53.66,25.08 v53.66,23.5
  Bottom 0.254: v53.66,23.5 55.56,25.4 J8.P3
N$14
  Top 0.254: R43.1 R44.1 | R44.1 R45.2 C34.1 | IC9.6 48.26,31.75 48.9,31.11 R44.1
N$15
  Top 0.254: R39.2 25.93,29 29.53,25.4 J6.P3
N$16
  Top 0.254: C31.1 R37.2 | R37.2 R38.1 R39.1 | R37.2 19.37,31.75 19.68,32.07 IC8.2
N$17  (via drill 0.6)
  Top 0.254: R5.P$2 34.29,83.19 31.43,86.04 31.43,89.22 28.26,92.39 28.26,93.03 25.72,95.57 25.72,96.84 24.45,98.11 21.91,98.11 20.95,99.06 18.1,99.06 15.24,96.2 15.24,91.12 9.84,85.72 9.84,78.42 8.57,77.15 v8.57,76.83 | R38.2 20.95,28.26 20.64,27.94 15.24,27.94 14.61,28.57 14.61,31.75 11.43,34.92 9.21,34.92 7.3,36.83 7.3,43.5 6.03,44.77 v6.03,49.85 | v9.21,60.01 9.21,58.42 v6.03,55.24
  Bottom 0.254: v8.57,76.83 8.57,72.07 11.11,69.53 11.11,68.9 9.53,67.31 9.53,61.91 9.21,61.59 v9.21,60.01 | v6.03,49.85 6.03,52.39 6.35,52.7 6.35,54.93 v6.03,55.24
N$18
  Top 0.254: R22.1 15.03,47.41 14.29,46.67 12.06,46.67 11.43,47.31 11.43,48.58 12.06,49.21 13.65,49.21 14.61,50.16 14.61,52.7 13.02,54.29 6.03,54.29 2.86,51.12 2.86,31.43 3.49,30.8 3.49,15.56 2.54,14.61 2.54,5.71 5.08,3.17 52.39,3.17 53.66,1.91 J13.P3
N$19
  Top 0.254: R5.P$1 36.83,81.31 36.83,82.23 38.52,83.92 R8.2
N$20
  Top 0.254: R36.2 23.28,42.76 23.5,42.55 23.5,35.24 29.53,29.21 36.51,29.21 36.83,28.89 36.83,28.26 37.78,27.3 39.37,27.3 40.96,25.72 40.96,23.18 41.91,22.23 J7.P3
N$21
  Top 0.254: R56.1 20,21.91 22.23,24.13 J5.P3
N$22
  Top 0.254: R35.1 IC8.6 | R35.1 R34.2 C27.1 | R35.1 R36.1
N$23
  Top 0.254: Q4.B 16.51,11.43 16.83,11.11 19.37,11.11 20,11.75 R56.2
N$24
  Top 0.254: R54.1 9.21,13.55 9.21,11.43 5.71,7.94 J9.P3
N$25
  Top 0.254: R54.2 11.75,13.65 12.06,13.34 12.06,12.7 12.21,12.55 Q3.B
N$26
  Top 0.254: R58.2 36.26,12.55 Q6.B
N$27  (via drill 0.6)
  Top 0.254: R53.1 R52.2 38.8,14.82 Q6.C 38.73,6.35 v38.1,5.71
  Bottom 0.254: v38.1,5.71 38.1,3.17 36.83,1.91 J11.P3
N$28
  Top 0.254: LED3.3 20.73,80.33 R10.2
N$29
  Top 0.254: LED3.1 20.73,82.23 R9.2
N$30
  Top 0.254: LED2.3 20.73,87.31 R7.2
N$31
  Top 0.254: LED2.1 20.73,89.22 R4.2
N$32
  Top 0.254: LED1.3 20.73,94.3 R3.2
N$33
  Top 0.254: LED1.1 20.73,96.2 R2.2
N$34
  Top 0.254: R10.1 25.4,80.33 29.05,76.68 31.59,76.68 32.86,75.41 UC1.46
N$35
  Top 0.254: R9.1 24.45,82.23 29.37,77.31 31.75,77.31 33.36,75.7 UC1.45
N$36
  Top 0.254: R7.1 24.13,87.31 25.08,86.36 25.08,82.55 29.69,77.95 33.97,77.95 34.36,77.56 UC1.43
N$37
  Top 0.254: R4.1 24.13,89.22 25.72,87.63 25.72,82.87 30,78.58 34.45,78.58 34.86,78.17 UC1.42
N$38
  Top 0.254: R3.1 24.13,94.3 26.35,92.08 26.35,83.19 30.32,79.22 34.77,79.22 35.36,78.62 UC1.41
N$39
  Top 0.254: R2.1 24.13,96.2 24.45,95.89 24.45,94.93 26.99,92.39 26.99,83.5 30.64,79.85 35.08,79.85 35.86,79.08 UC1.40
N$40
  Top 0.254: R59.1 14.61,47.94 15.88,49.21 R21.2
N$41
  Top 0.254: IC6.2 R25.2 R26.2
N$42
  Top 0.254: IC5.7 C19.2 | IC5.7 IC5.6 | IC5.7 19.68,55.24 19.27,54.83 R20.2
N$43
  Top 0.254: R15.1 22.96,59.48 | IC5.5 22.23,57.78 23.07,58.63 R15.1 | R15.1 23.18,59.27 C22.1
N$44  (via drill 0.6)
  Top 0.254: R51.1 R50.2 26.74,14.82 Q5.C 26.67,6.67 v24.77,4.76
  Bottom 0.254: v24.77,4.76 24.77,3.17 23.5,1.91 J10.P3
N$45
  Top 0.254: R15.2 21.27,59.48 21.38,59.58 R13.1 21.27,60.86 C19.1 19.68,60.64 20.11,61.06
N$46
  Top 0.254: IC6.1 43.81,50.16 43.5,49.85 R24.2 43.5,49 R25.1
N$47
  Top 0.254: R57.2 24.2,12.55 Q5.B
N$48
  Top 0.254: J8.P2 62.55,17.78 63.5,18.73 63.5,21.91 64.13,22.54 R60.2
N$56
  Top 0.406: JP1.2 JP1.1 66.67,79.69 66.04,80.33 D1.A
N$57
  Top 0.254: R55.1 3.81,14.92 5.71,16.83 J4.P3
N$64
  Top 0.406: JP1.10 JP1.9 66.67,65.09 66.04,64.45 D2.C
N$66
  Top 0.254: R55.2 3.88,12.55 Q2.B
N$67
  Top 0.254: C21.2 IC6.7 IC6.6 IC6.3
N$69
  Top 0.254: R16.1 48.36,59.48 | R16.1 48.58,59.27 C23.1 | IC6.5 47.62,57.78 48.48,58.63 R16.1
N$71
  Top 0.254: R16.2 46.67,59.48 46.77,59.58 R14.1 46.67,60.86 C21.1 45.29,61.06
PROC_ADC
  Top 0.254: 49.53,37.47 IC9.8 | 49.53,37.47 42.55,37.47 36.83,31.75 30.8,31.75 26.04,36.51 26.04,45.4 27.94,47.31 27.94,53.98 29.84,55.88 30.48,55.88 32.07,57.47 32.07,61.59 33.86,63.38 UC1.17 | 49.53,37.47 50.64,37.47 50.96,37.78 C28.2 51.7,38.36 51.91,38.58 51.91,43.02 51.59,43.34 51.02,43.34 R33.1
RANGE_SW  (via drill 0.6)
  Top 0.254: SW4.A1 SW4.A2 | UC1.11 29.66,67.92 29.37,67.63 29.37,65.09 26.99,62.71 20.32,62.71 18.41,64.61 14.92,64.61 13.18,66.36 13.18,67.79 11.75,69.22 v10,69.22
  Bottom 0.254: v10,69.22 8.89,70.33 7.66,71.56 SW4.A1
RESET  (via drill 0.6)
  Top 0.254: v53.66,97.16 53.66,99.38 52.07,100.97 43.81,100.97 43.59,101.19 SW2.B v38.73,101.19 SW2.B' | v25.08,72.71 R11.1 27.3,72.92 v27.3,74.93 | v25.08,69.53 25.47,69.92 UC1.7 | v36.51,86.36 36.51,91.12 v40.64,95.25
  Bottom 0.254: v53.66,97.16 JP2.10 | v25.08,69.53 v25.08,72.71 | v27.3,74.93 27.94,74.3 34.61,74.3 40.01,79.69 40.01,82.87 v36.51,86.36 | v40.64,95.25 41.59,95.25 43.18,96.84 43.18,99.06 41.05,101.19 v38.73,101.19
RX
  Top 0.254: UC1.31 40.73,70.42 44.45,74.14 44.45,76.2 43.81,76.83 43.81,77.15 43.5,77.47 43.5,91.76 44.77,93.03 49.85,93.03 52.07,95.25 52.07,98.74 51.12,99.69 45.72,99.69 42.23,96.2 36.2,96.2 35.56,96.84 JP3.4
SHAPE_ADC
  Top 0.254: R40.1 C32.2 38.31,29 38.1,29.21 38.1,30.48 | 38.1,30.48 30.16,30.48 24.77,35.88 24.77,46.04 26.67,47.94 26.67,54.61 27.62,55.56 27.62,58.9 32.86,64.13 UC1.15 | 38.1,30.48 38.1,31.11 39.79,32.8 IC9.1
START  (via drill 0.6)
  Top 0.254: Q2.C 6.35,19.37 7.3,20.32 7.3,25.72 8.57,26.99 R47.1 7.2,28.04 3.49,31.75 3.49,40.64 v3.81,40.96 | UC1.22 36.36,62.08 34.61,60.33 34.61,56.2 31.75,53.34 31.11,53.34 30.48,52.7 30.48,46.04 28.57,44.13 28.57,42.86 v28.89,42.55
  Bottom 0.254: v28.89,42.55 28.57,42.23 27.62,42.23 27.3,41.91 27.3,37.78 26.67,37.15 16.51,37.15 11.75,41.91 8.57,41.91 7.62,40.96 v3.81,40.96
TX
  Top 0.254: UC1.30 41.02,69.92 45.09,73.98 45.09,76.52 44.45,77.15 44.45,77.47 44.13,77.79 44.13,91.44 45.09,92.39 50.16,92.39 52.7,94.93 52.7,99.06 51.44,100.33 45.4,100.33 44.45,99.38 38.73,99.38 38.1,98.74 JP3.5
UNI
  Top 0.254: R14.2 48.58,61.06 48.58,62.87 47.65,63.8 IC4.4
UNI_OUT  (via drill 0.6)
  Top 0.254: v61.59,46.35 43.81,46.35 43.5,46.67 R24.1 | v66.04,46.35 66.04,25.4 67.63,23.81 67.63,20.32 60.64,13.34 45.72,13.34 41.91,9.53 J12.P3
  Bottom 0.254: v66.04,46.35 v61.59,46.35
VCC  (via drill 0.6)
  Top 0.254: R53.2 42.86,12.38 40.01,9.53 40.01,5.4 38.42,3.81 29.21,3.81 28.26,4.76 28.26,8.26 30.8,10.79 R51.2 | R60.1 | 49.21,14.29 49.53,13.97 60.33,13.97 65.09,18.73 65.09,20
  Top 0.305: v64.45,53.98 64.45,25.4 66.36,23.5 66.36,20.95 66.04,20.64 R60.1 | 49.21,14.29 45.09,14.29 43.92,13.12 R53.2 | R60.1 65.09,20 65.09,19.68
  Top 0.406: C3.+ 60.64,76.02 60.64,74.3 58.42,72.07 58.42,67.31 59.05,66.67 v59.05,57.15 | 50.91,82.87 IC1.3 50.89,82.14 54.93,78.11 59.37,78.11 60.01,77.47 60.01,76.2 C3.+ | 17.04,59.16 12.7,63.5 7.62,63.5 5.08,66.04 5.08,69.22 3.49,70.8 C8.+ 3.67,71.75 5.08,71.75 6.01,72.68 IC3.3 | 17.04,59.16 C18.1 18.1,58.1 18.41,57.78 IC5.8 | v17.14,56.2 17.04,56.3 17.04,59.16 | v42.55,55.24 42.55,58.74 42.86,59.05 43.4,59.05 C20.1 43.5,58.1 43.81,57.78 IC6.8 | D1.C 65.09,85.72 63.5,84.14 63.5,80.33 60.82,77.65 C3.+
  Bottom 0.305: v64.45,53.98 61.28,57.15 v59.05,57.15
  Bottom 0.406: 42.55,54.93 23.81,54.93 23.5,55.24 18.1,55.24 v17.14,56.2 | v59.05,57.15 56.83,54.93 48.26,54.93 48.1,55.09 47.15,55.09 46.99,54.93 42.55,54.93 | 42.55,54.93 v42.55,55.24
VEE  (via drill 0.6)
  Top 0.254: R27.1 36.2,48.9 v35.56,49.53
  Top 0.406: C25.2 48.26,49.85 47.62,50.48 IC6.4 v47.62,53.98 | IC5.4 22.23,50.16 21.91,49.85 C24.2 22.12,49.11 23.18,50.16 v23.18,53.98 | C10.- 60.47,68.58 60.33,68.44 v60.33,55.88 | C10.- 61.28,68.58 | D2.A 66.04,60.01 65.09,60.96 63.18,60.96 61.28,62.87 61.28,67.31 60.82,67.77 C10.-
  Bottom 0.254: v35.56,49.53 30.8,49.53 30.16,50.16 30.16,53.98
  Bottom 0.406: v23.18,53.98 30.16,53.98 v47.62,53.98 57.15,53.98 59.05,55.88 v60.33,55.88
VOCT_ADC
  Top 0.254: R37.1 C31.2 17.04,29 16.83,29.21 16.83,31.43 17.14,31.75 17.78,31.75 18.41,32.38 IC8.1 18.36,33.34 14.92,33.34 14.29,33.97 14.29,34.92 14.92,35.56 14.92,42.55 16.19,43.81 18.1,43.81 19.37,45.09 21.91,45.09 25.4,48.58 25.4,55.24 26.35,56.2 26.35,59.21 31.86,64.72 UC1.13

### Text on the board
tPlace: Tides
bPlace: Tides | Red stripe
tNames: SYSBOOT | RESET | Bipolar output | Offset adjust. | cc-by-sa Olivier Gillet, 2015. v4
bNames: FTDI dongle | mini JTAG | GND | RX< | TX> | JTMS | JTCK | JTDO | JTDI | RESET | +12V | GND | GND | GND | -12V | cc-by-sa Olivier Gillet, 2015. v4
